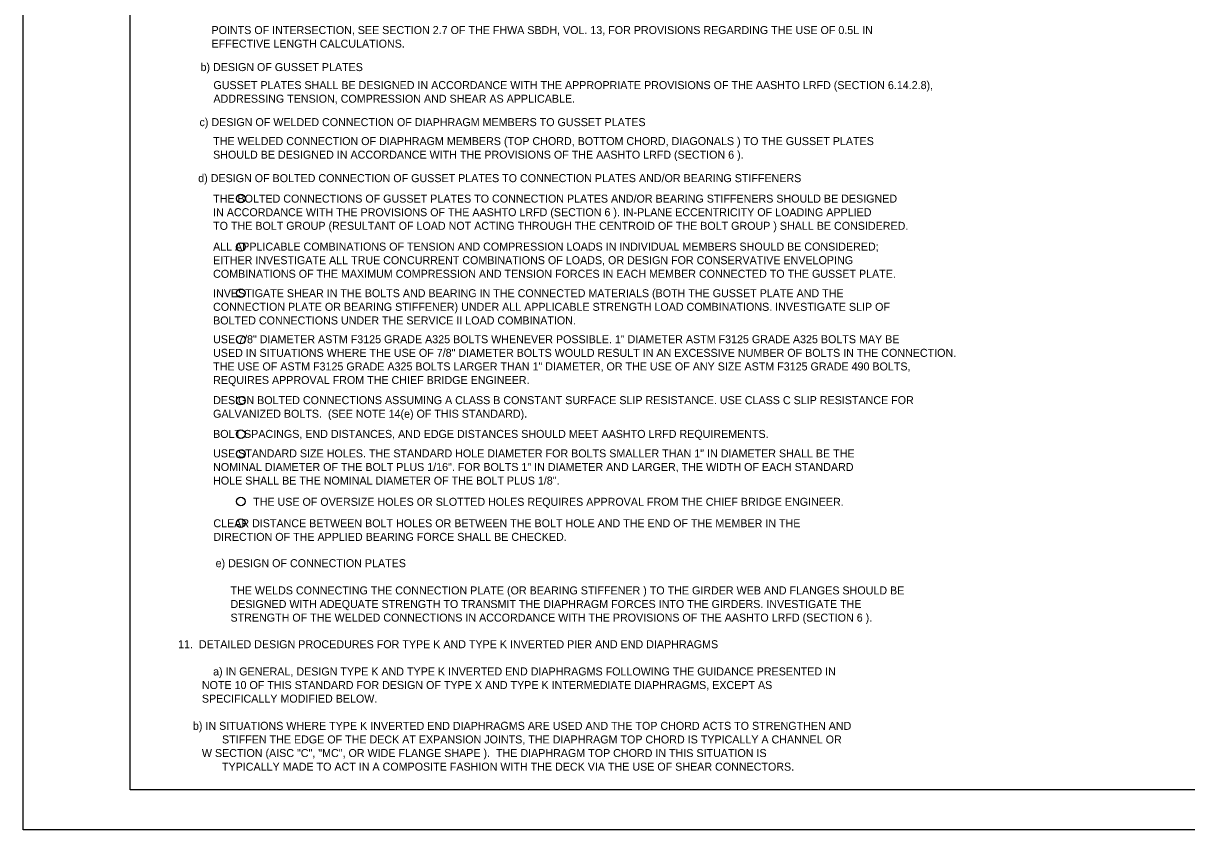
# Model space of a CAD drawing. Extents: x 634656 to 641360, y 298715 to 301183.
# Drawn here: x 637375.4 to 637811.5, y 298725 to 299027.4 of the extents above; entities that cross this region are included whole.
import ezdxf

# ---------------------------------------------------------------- set-up
doc = ezdxf.new("R2010")
doc.units = 0
for name, color, linetype in [('1', 7, 'Continuous'), ('2', 7, 'Continuous'), ('PLT-BNDY', 7, 'Continuous')]:
    doc.layers.add(name, color=color, linetype=linetype)

msp = doc.modelspace()

# ---------------------------------------------------------------- linework, layer by layer
at = {"layer": '1'}
for centre in [(637456.92, 298961.66), (637456.92, 298943.48), (637456.92, 298926.12), (637456.92, 298908.74), (637456.92, 298885.87), (637456.92, 298873.33), (637456.92, 298865.87), (637456.92, 298848.05), (637456.92, 298839.92)]:
    msp.add_circle(centre, 1.61, dxfattribs=at)
at = {"layer": '2'}
for p, q in [((637415.43, 298739.99), (637415.43, 299303.99)), ((638201.43, 298739.99), (637415.43, 298739.99))]:
    msp.add_line(p, q, dxfattribs=at)
at = {"layer": 'PLT-BNDY'}
msp.add_lwpolyline([(637375.43, 299318.99), (638216.43, 299318.99), (638216.43, 298724.99), (637375.43, 298724.99)], close=True, dxfattribs=at)

# ---------------------------------------------------------------- texts
at = {"layer": '1'}
for s, height, p in [('        POINTS OF INTERSECTION, SEE SECTION 2.7 OF THE FHWA SBDH, VOL. 13, FOR PROVISIONS REGARDING THE USE OF 0.5L IN', 2.99987, (637437.06, 299023.31)), ('        EFFECTIVE LENGTH CALCULATIONS. ', 2.9999, (637437.06, 299018.21)), ('   b) DESIGN OF GUSSET PLATES', 2.9999, (637438.51, 299009.43)), ('        GUSSET PLATES SHALL BE DESIGNED IN ACCORDANCE WITH THE APPROPRIATE PROVISIONS OF THE AASHTO LRFD (SECTION 6.14.2.8), ', 2.99987, (637437.78, 299002.67)), ('        ADDRESSING TENSION, COMPRESSION AND SHEAR AS APPLICABLE.', 2.9999, (637437.78, 298997.57)), ('   c) DESIGN OF WELDED CONNECTION OF DIAPHRAGM MEMBERS TO GUSSET PLATES', 2.9999, (637438.14, 298988.79)), ('        THE WELDED CONNECTION OF DIAPHRAGM MEMBERS (TOP CHORD, BOTTOM CHORD, DIAGONALS ) TO THE GUSSET PLATES', 2.99987, (637437.66, 298981.68)), ('        SHOULD BE DESIGNED IN ACCORDANCE WITH THE PROVISIONS OF THE AASHTO LRFD (SECTION 6 ).', 2.9999, (637437.66, 298976.58)), ('   d) DESIGN OF BOLTED CONNECTION OF GUSSET PLATES TO CONNECTION PLATES AND/OR BEARING STIFFENERS', 2.9999, (637437.66, 298967.79)), ('        THE BOLTED CONNECTIONS OF GUSSET PLATES TO CONNECTION PLATES AND/OR BEARING STIFFENERS SHOULD BE DESIGNED', 2.99987, (637437.66, 298960.11)), ('        IN ACCORDANCE WITH THE PROVISIONS OF THE AASHTO LRFD (SECTION 6 ). IN-PLANE ECCENTRICITY OF LOADING APPLIED', 2.99987, (637437.66, 298955.01)), ('        TO THE BOLT GROUP (RESULTANT OF LOAD NOT ACTING THROUGH THE CENTROID OF THE BOLT GROUP ) SHALL BE CONSIDERED.', 2.99987, (637437.66, 298949.91)), ('        ALL APPLICABLE COMBINATIONS OF TENSION AND COMPRESSION LOADS IN INDIVIDUAL MEMBERS SHOULD BE CONSIDERED;', 2.99987, (637437.66, 298942.13)), ('        EITHER INVESTIGATE ALL TRUE CONCURRENT COMBINATIONS OF LOADS, OR DESIGN FOR CONSERVATIVE ENVELOPING', 2.99987, (637437.66, 298937.03)), ('        COMBINATIONS OF THE MAXIMUM COMPRESSION AND TENSION FORCES IN EACH MEMBER CONNECTED TO THE GUSSET PLATE.', 2.99987, (637437.66, 298931.93)), ('        INVESTIGATE SHEAR IN THE BOLTS AND BEARING IN THE CONNECTED MATERIALS (BOTH THE GUSSET PLATE AND THE', 2.99987, (637437.66, 298924.64)), ('        CONNECTION PLATE OR BEARING STIFFENER) UNDER ALL APPLICABLE STRENGTH LOAD COMBINATIONS. INVESTIGATE SLIP OF', 2.99987, (637437.66, 298919.54)), ('        BOLTED CONNECTIONS UNDER THE SERVICE II LOAD COMBINATION.', 2.9999, (637437.66, 298914.44)), ('        USE 7/8" DIAMETER ASTM F3125 GRADE A325 BOLTS WHENEVER POSSIBLE. 1" DIAMETER ASTM F3125 GRADE A325 BOLTS MAY BE', 2.99987, (637437.66, 298907.39)), ('        USED IN SITUATIONS WHERE THE USE OF 7/8" DIAMETER BOLTS WOULD RESULT IN AN EXCESSIVE NUMBER OF BOLTS IN THE CONNECTION.', 2.99987, (637437.66, 298902.29)), ('        THE USE OF ASTM F3125 GRADE A325 BOLTS LARGER THAN 1" DIAMETER, OR THE USE OF ANY SIZE ASTM F3125 GRADE 490 BOLTS,', 2.99987, (637437.66, 298897.19)), ('        REQUIRES APPROVAL FROM THE CHIEF BRIDGE ENGINEER.', 2.9999, (637437.66, 298892.09)), ('        DESIGN BOLTED CONNECTIONS ASSUMING A CLASS B CONSTANT SURFACE SLIP RESISTANCE. USE CLASS C SLIP RESISTANCE FOR', 2.99987, (637437.66, 298884.56)), ('        GALVANIZED BOLTS.  (SEE NOTE 14(e) OF THIS STANDARD).', 2.9999, (637437.66, 298879.46)), ('        BOLT SPACINGS, END DISTANCES, AND EDGE DISTANCES SHOULD MEET AASHTO LRFD REQUIREMENTS.', 2.9999, (637437.66, 298871.89)), ('        USE STANDARD SIZE HOLES. THE STANDARD HOLE DIAMETER FOR BOLTS SMALLER THAN 1" IN DIAMETER SHALL BE THE', 2.99987, (637437.66, 298864.59)), ('        NOMINAL DIAMETER OF THE BOLT PLUS 1/16". FOR BOLTS 1" IN DIAMETER AND LARGER, THE WIDTH OF EACH STANDARD', 2.99987, (637437.66, 298859.49)), ('        HOLE SHALL BE THE NOMINAL DIAMETER OF THE BOLT PLUS 1/8".', 2.9999, (637437.66, 298854.39)), ('THE USE OF OVERSIZE HOLES OR SLOTTED HOLES REQUIRES APPROVAL FROM THE CHIEF BRIDGE ENGINEER.', 2.9999, (637461.58, 298846.44)), ('        CLEAR DISTANCE BETWEEN BOLT HOLES OR BETWEEN THE BOLT HOLE AND THE END OF THE MEMBER IN THE', 2.9999, (637437.77, 298838.39)), ('        DIRECTION OF THE APPLIED BEARING FORCE SHALL BE CHECKED.', 2.9999, (637437.77, 298833.29)), ('e) DESIGN OF CONNECTION PLATES', 2.9999, (637447.52, 298823.42)), ('     THE WELDS CONNECTING THE CONNECTION PLATE (OR BEARING STIFFENER ) TO THE GIRDER WEB AND FLANGES SHOULD BE', 2.99987, (637447.52, 298813.22)), ('     DESIGNED WITH ADEQUATE STRENGTH TO TRANSMIT THE DIAPHRAGM FORCES INTO THE GIRDERS. INVESTIGATE THE', 2.99987, (637447.52, 298808.12)), ('     STRENGTH OF THE WELDED CONNECTIONS IN ACCORDANCE WITH THE PROVISIONS OF THE AASHTO LRFD (SECTION 6 ).', 2.99987, (637447.52, 298803.02)), ('11.  DETAILED DESIGN PROCEDURES FOR TYPE K AND TYPE K INVERTED PIER AND END DIAPHRAGMS', 2.9999, (637433.45, 298793.04)), (' a) IN GENERAL, DESIGN TYPE K AND TYPE K INVERTED END DIAPHRAGMS FOLLOWING THE GUIDANCE PRESENTED IN', 2.9999, (637445.45, 298782.84)), ('        NOTE 10 OF THIS STANDARD FOR DESIGN OF TYPE X AND TYPE K INTERMEDIATE DIAPHRAGMS, EXCEPT AS', 2.9999, (637433.45, 298777.74)), ('        SPECIFICALLY MODIFIED BELOW.', 2.9999, (637433.45, 298772.64)), ('     b) IN SITUATIONS WHERE TYPE K INVERTED END DIAPHRAGMS ARE USED AND THE TOP CHORD ACTS TO STRENGTHEN AND', 2.99987, (637433.45, 298762.44)), ('    STIFFEN THE EDGE OF THE DECK AT EXPANSION JOINTS, THE DIAPHRAGM TOP CHORD IS TYPICALLY A CHANNEL OR', 2.99987, (637445.45, 298757.34)), ('        W SECTION (AISC "C", "MC", OR WIDE FLANGE SHAPE ).  THE DIAPHRAGM TOP CHORD IN THIS SITUATION IS', 2.99987, (637433.45, 298752.24)), ('    TYPICALLY MADE TO ACT IN A COMPOSITE FASHION WITH THE DECK VIA THE USE OF SHEAR CONNECTORS.', 2.9999, (637445.45, 298747.14))]:
    msp.add_text(s, height=height, dxfattribs=at).set_placement(p)

doc.saveas('drawing.dxf')
